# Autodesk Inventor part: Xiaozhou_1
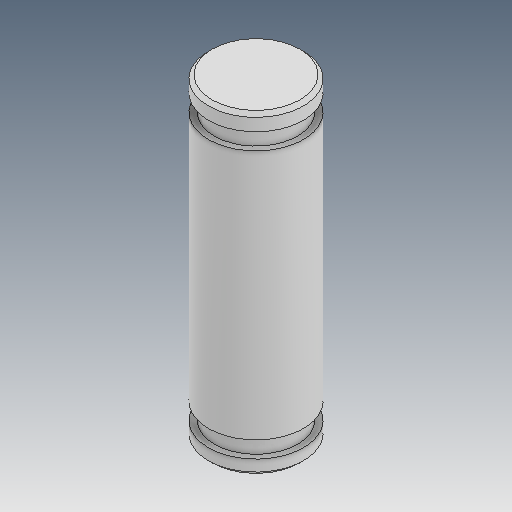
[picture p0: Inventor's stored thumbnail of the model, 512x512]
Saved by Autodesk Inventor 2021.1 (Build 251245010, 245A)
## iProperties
Created: 2021-05
Part Number: Xiaozhou_1
Material: Ogólny
Document SubType Name: Modeling
Designer: user
Density: 1 g/cm^3
Appearance: Domyślna
Author: user
Revision Number: ÈÎºÎ
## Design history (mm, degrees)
feature "ÊäÈë1"
node "Bryła1"
